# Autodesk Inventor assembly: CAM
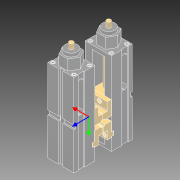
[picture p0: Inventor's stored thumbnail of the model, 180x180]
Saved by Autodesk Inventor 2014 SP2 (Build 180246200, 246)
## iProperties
Created: 2005-05
Part Number: CAM
Document SubType Name: Assembly
Designer: Administrator
Mass: 8688.92 g
Surface Area: 10150.2 cm^2
Volume: 8675.91 cm^3
Density: 1.0015 g/cm^3
Author: Administrator
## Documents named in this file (3)
- Z:\VDW-Nachwuchsstiftung Intern\Mitarbeiter Ablage\Steffen Krauth\IVCAM\KnowledgeBase Daten\NADELHALTER_OBEN\NADELHALTER_OBEN.IAM
- Z:\VDW-Nachwuchsstiftung Intern\Mitarbeiter Ablage\Steffen Krauth\IVCAM\KnowledgeBase Daten\NADELHALTER_OBEN\DesignModel.iam
- Z:\VDW-Nachwuchsstiftung Intern\Mitarbeiter Ablage\Steffen Krauth\IVCAM\KnowledgeBase Daten\NADELHALTER_OBEN\CAM.IPT
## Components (2 placed, 2 different names)
1. DesignModel:1 [sub-assembly]
2. CAM:1
